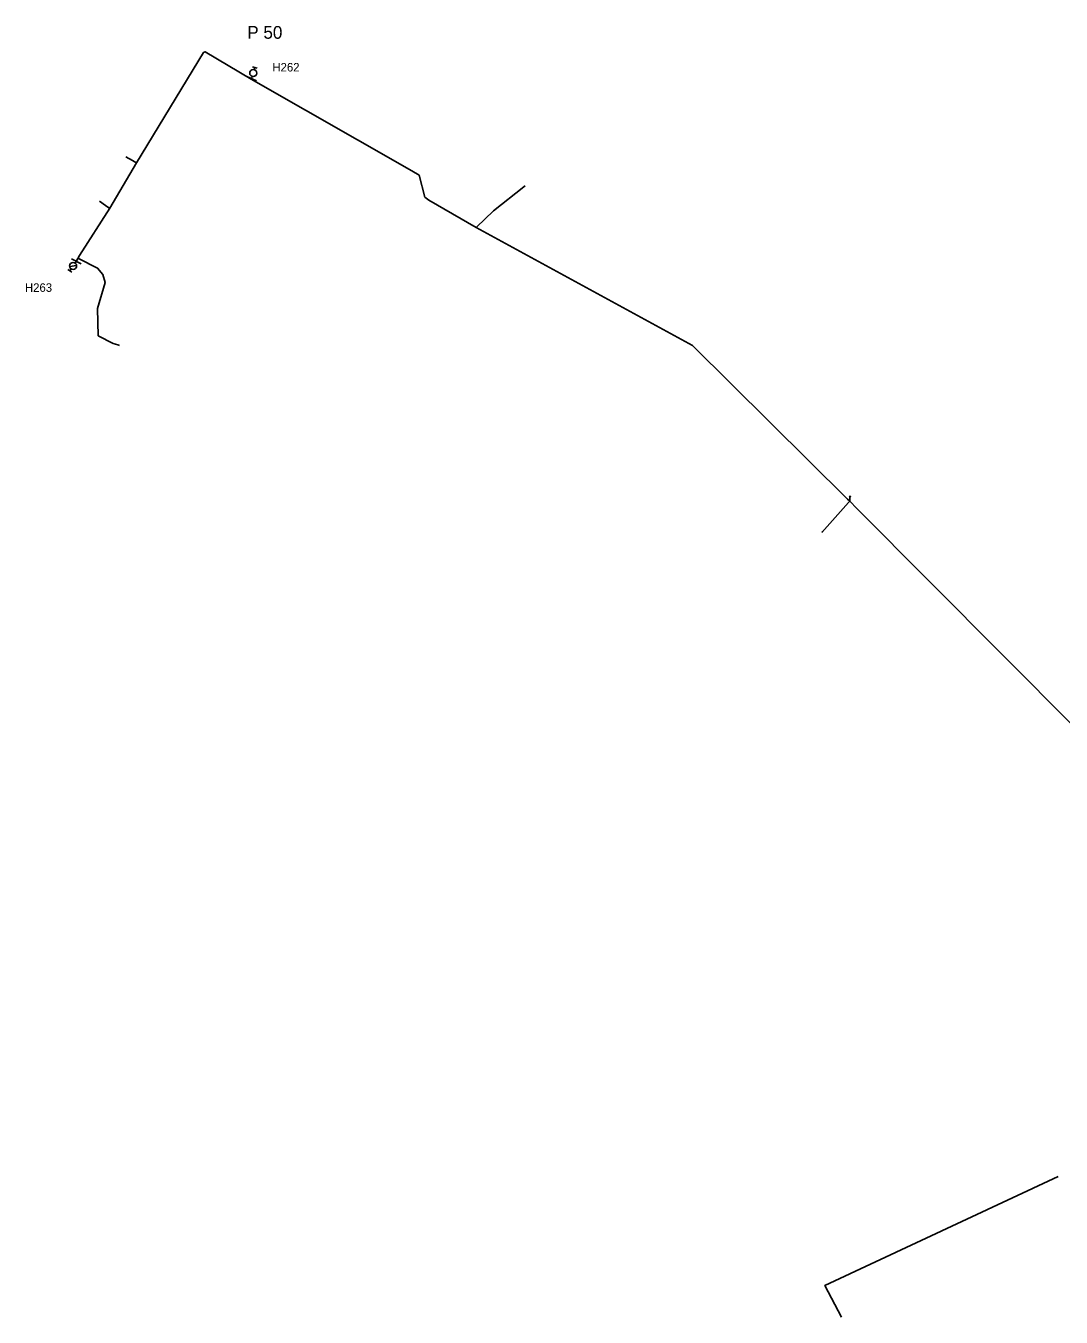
# Model space of a CAD drawing. Extents: x -548873 to -538270, y -1201997 to -1192514.
# Drawn here: x -545561.7 to -545318.1, y -1193096.5 to -1192792.5 of the extents above; entities that cross this region are included whole.
import ezdxf

# ---------------------------------------------------------------- set-up
doc = ezdxf.new("R2010")
doc.units = 0
for name, color, linetype in [('KN_HRAN_STÁTNÍ', 7, 'Continuous'), ('KN_PARC_Č', 7, 'Continuous'), ('KN_VKP_HRAN_SPORNÁ', 7, 'Continuous'), ('PK_PARC_Čv', 7, 'Continuous'), ('Vrstva 29', 7, 'Continuous'), ('Vrstva 39', 7, 'Continuous')]:
    doc.layers.add(name, color=color, linetype=linetype)

# ---------------------------------------------------------------- blocks, each defined once
blk = doc.blocks.new('160')
at = {"layer": 'KN_HRAN_STÁTNÍ'}
blk.add_circle((0, 0), 0.0458, dxfattribs=at)
blk = doc.blocks.new('132')
at = {"layer": 'KN_HRAN_STÁTNÍ'}
for p, q in [((0.3, 0), (0, 0)), ((1.96, 0), (2.52, 0)), ((2.52, 0.58), (2.52, -0.58))]:
    blk.add_line(p, q, dxfattribs=at)
blk.add_circle((1.13, 0.01), 0.825, dxfattribs=at)
blk = doc.blocks.new('133')
at = {"layer": 'KN_HRAN_STÁTNÍ'}
for p, q in [((0.28, 0), (0, 0)), ((0.54, 0.58), (1.7, -0.58)), ((1.94, 0), (2.52, 0)), ((2.52, 0.58), (2.52, -0.58))]:
    blk.add_line(p, q, dxfattribs=at)
blk.add_circle((1.11, 0), 0.825, dxfattribs=at)
blk = doc.blocks.new('150')
at = {"layer": 'KN_HRAN_STÁTNÍ'}
blk.add_line((0, 1.27), (0, -1.27), dxfattribs=at)
blk = doc.blocks.new('124')
at = {"layer": 'KN_HRAN_STÁTNÍ'}
for q in [(-0.19, 1.22), (-0.19, 0.92), (0.19, 1.22), (0, 0), (0.19, 0.92)]:
    blk.add_line((0, 1.07), q, dxfattribs=at)

msp = doc.modelspace()

# ---------------------------------------------------------------- linework, layer by layer
at = {"layer": 'KN_PARC_Č'}
for points in [[(-545535.61, -1192824.77), (-545535.78, -1192824.64), (-545536.58, -1192824.18), (-545538.121, -1192823.294)], [(-545455.76, -1192839.99), (-545455.66, -1192839.9), (-545451.65, -1192836.01), (-545444.48, -1192830.39), (-545444.17, -1192830.18)], [(-545541.93, -1192835.4), (-545542.12, -1192835.3), (-545542.89, -1192834.78), (-545544.353, -1192833.792)], [(-545549.385, -1192847.171), (-545549.24, -1192847.24), (-545544.79, -1192849.5), (-545543.58, -1192851), (-545542.99, -1192852.9), (-545544.76, -1192859.04), (-545544.61, -1192865.45), (-545541.08, -1192867.29), (-545540.05, -1192867.61), (-545539.63, -1192867.76)], [(-545367.82, -1192904.39), (-545368.15, -1192904.69), (-545374.4, -1192911.74)], [(-545374.304, -1192911.632), (-545374.444, -1192911.505)], [(-545318.806, -1193063.345), (-545373.699, -1193088.999), (-545369.827, -1193096.46)]]:
    msp.add_lwpolyline(points, dxfattribs=at)
at = {"layer": 'KN_VKP_HRAN_SPORNÁ'}
for points in [[(-545519.49, -1192798.62), (-545519.88, -1192798.79), (-545535.61, -1192824.77), (-545541.93, -1192835.4), (-545549.06, -1192846.53), (-545549.7, -1192847.79)], [(-545367.82, -1192904.39), (-545368.37, -1192903.88), (-545404.82, -1192867.78), (-545455.76, -1192839.99), (-545466.86, -1192833.57), (-545467.82, -1192832.8), (-545469.15, -1192827.62), (-545470.86, -1192826.61), (-545508.618, -1192805.053), (-545519.49, -1192798.62)], [(-545255, -1193035.68), (-545255.25, -1193035.12), (-545296.34, -1192977.05), (-545296.63, -1192976.58), (-545296.86, -1192976.21), (-545297.54, -1192975.1), (-545297.55, -1192975.07), (-545366.21, -1192906.11), (-545367.82, -1192904.39)]]:
    msp.add_lwpolyline(points, dxfattribs=at)
at = {"layer": 'PK_PARC_Čv'}
for points in [[(-545508.618, -1192805.053), (-545508.53, -1192804.91), (-545508.47, -1192804.71)], [(-545549.7, -1192847.79), (-545549.77, -1192847.92), (-545549.84, -1192848.04), (-545549.89, -1192848.11)]]:
    msp.add_lwpolyline(points, dxfattribs=at)

# ---------------------------------------------------------------- block references
for name, p, xscale, yscale, rotation in [('132', (-545508.47, -1192804.71), 0.9999999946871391, 0.9999999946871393, 73.99999975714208), ('150', (-545508.53, -1192804.91), 0.9999999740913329, 0.9999999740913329, 65.99999939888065), ('133', (-545549.89, -1192848.11), 1.000000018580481, 1.000000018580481, -125.00000023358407), ('150', (-545549.77, -1192847.92), 1.0000000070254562, 1.0000000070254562, 61.000001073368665)]:
    msp.add_blockref(name, p, dxfattribs=dict(at, xscale=xscale, yscale=yscale, rotation=rotation))
at = {"layer": 'Vrstva 29'}
for p, xscale, yscale, rotation in [((-545519.49, -1192798.62), 1.0002788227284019, 1.0002788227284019, -3.2906995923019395), ((-545549.7, -1192847.79), 1.0000000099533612, 1.0000000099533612, -116.000000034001), ((-545367.82, -1192904.39), 1.0000000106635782, 1.0000000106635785, 45.99999834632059)]:
    msp.add_blockref('160', p, dxfattribs=dict(at, xscale=xscale, yscale=yscale, rotation=rotation))
at = {"layer": 'Vrstva 39'}
msp.add_blockref('124', (-545367.82, -1192904.39), dxfattribs=at)

# ---------------------------------------------------------------- texts
at = {"layer": 'PK_PARC_Čv'}
for s, height, p in [('P 50', 3, (-545509.56, -1192795.54)), ('H262', 2, (-545503.66, -1192803.24)), ('H263', 2, (-545561.87, -1192855.11))]:
    msp.add_text(s, height=height, dxfattribs=at).set_placement(p)

doc.saveas('drawing.dxf')
